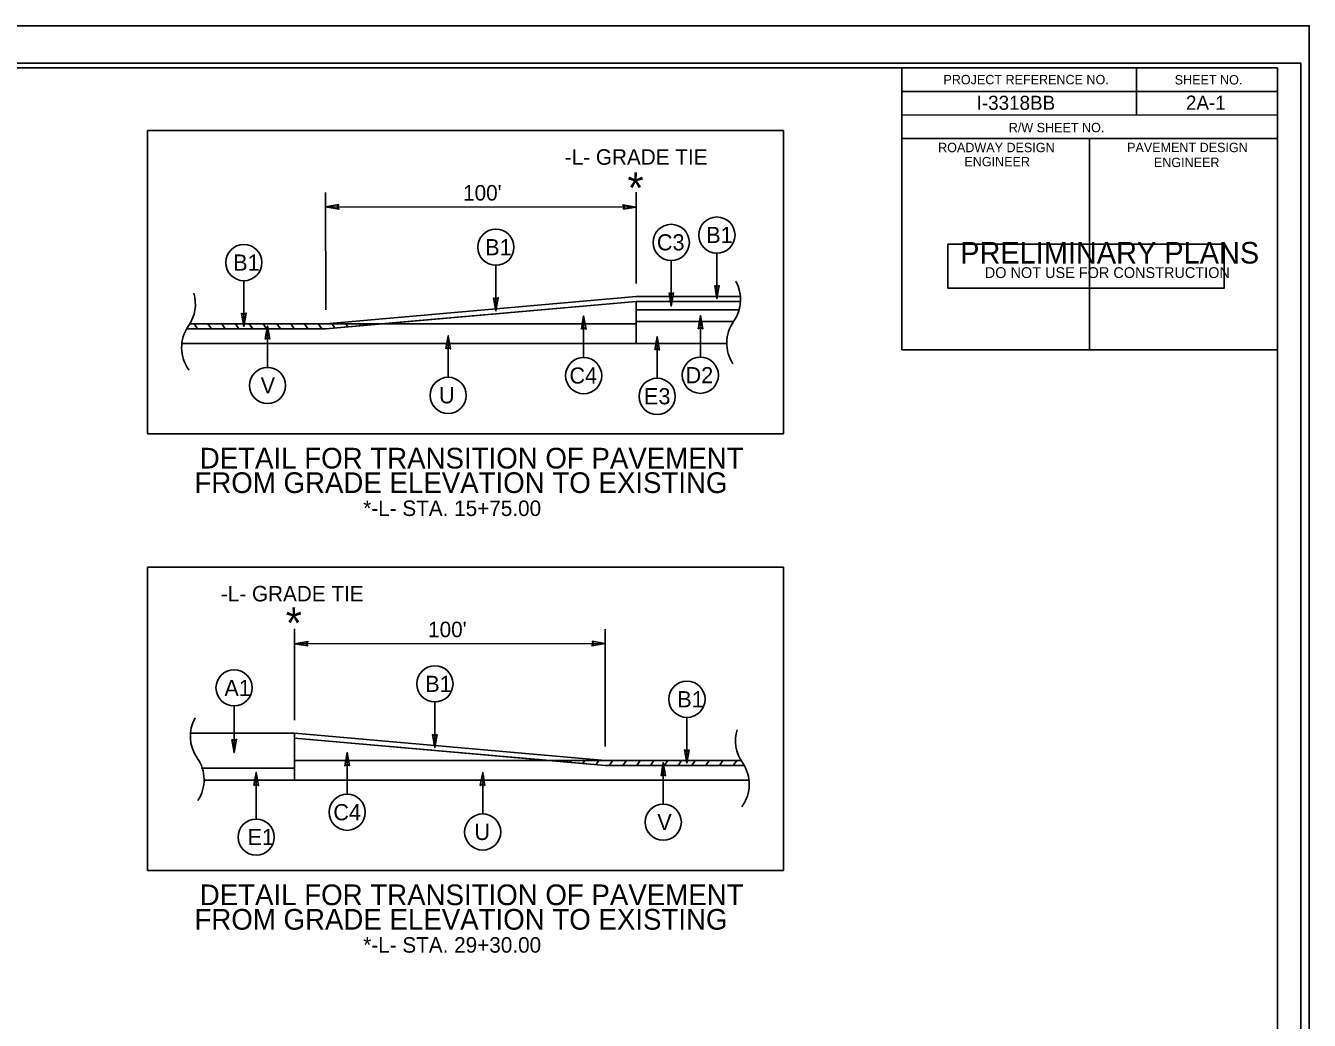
# Model space of a CAD drawing. Extents: x 2241081 to 2251104, y 658534 to 663427.
# Drawn here: x 2248635 to 2249319, y 662385 to 662914 of the extents above; entities that cross this region are included whole.
import ezdxf

# ---------------------------------------------------------------- set-up
doc = ezdxf.new("R2010")
doc.units = 0
for name, color, linetype in [('Old_Level_2', 7, 'Continuous'), ('Prop Dimension Text', 7, 'Continuous'), ('Prop Shade Medium', 7, 'Continuous'), ('Sheet Cutting Line CELL', 7, 'Continuous'), ('Sheet Data Field CELL', 7, 'Continuous'), ('Sheet Plan CELL', 7, 'Continuous'), ('Sheet Plot Border Inside CELL', 7, 'Continuous'), ('Sheet Plot Border Outside CELL', 7, 'Continuous'), ('Sheet Sticker Preliminary CELL', 7, 'Continuous'), ('Typical ID Circle CELL', 7, 'Continuous'), ('Typical Terminator CELL', 7, 'Continuous'), ('Typical Text ID Circle CELL', 7, 'Continuous'), ('Typical Text Label CELL', 7, 'Continuous')]:
    doc.layers.add(name, color=color, linetype=linetype)

msp = doc.modelspace()

# ---------------------------------------------------------------- linework, layer by layer
at = {"layer": 'Old_Level_2'}
for p, q in [((2248795.19, 662755.46), (2248960.58, 662770.04)), ((2248960.58, 662770.04), (2249016.04, 662770.04)), ((2248960.58, 662767.43), (2248824.7, 662755.46)), ((2248960.58, 662767.43), (2248960.58, 662744.97)), ((2249016.08, 662767.43), (2248960.58, 662767.43)), ((2249015.34, 662762.91), (2248960.58, 662762.91)), ((2249012.38, 662756.78), (2248960.58, 662756.78)), ((2248795.19, 662752.86), (2248721.13, 662752.86)), ((2248795.19, 662755.46), (2248722.82, 662755.46)), ((2248726.96, 662752.86), (2248725.12, 662755.46)), ((2248734.31, 662752.86), (2248732.47, 662755.46)), ((2248741.66, 662752.86), (2248739.82, 662755.46)), ((2248749, 662752.86), (2248747.17, 662755.46)), ((2248756.35, 662752.86), (2248754.51, 662755.46)), ((2248763.7, 662752.86), (2248761.86, 662755.46)), ((2248771.05, 662752.86), (2248769.21, 662755.46)), ((2248778.4, 662752.86), (2248776.56, 662755.46)), ((2248785.74, 662752.86), (2248783.91, 662755.46)), ((2248793.09, 662752.86), (2248791.31, 662755.38)), ((2248795.19, 662755.46), (2248960.58, 662755.46)), ((2248795.19, 662752.86), (2248824.7, 662755.46)), ((2248800.13, 662753.29), (2248798.6, 662755.46)), ((2248807.05, 662753.9), (2248805.95, 662755.46)), ((2248813.97, 662754.51), (2248813.3, 662755.46)), ((2248820.88, 662755.12), (2248820.64, 662755.46)), ((2248795.19, 662744.97), (2248718.56, 662744.97)), ((2248960.58, 662744.97), (2248795.19, 662744.97)), ((2249008.75, 662744.97), (2248960.58, 662744.97)), ((2248778.62, 662537.54), (2248723.16, 662537.54)), ((2248778.62, 662537.54), (2248778.62, 662512.48)), ((2248778.62, 662537.54), (2248944.01, 662522.96)), ((2248778.62, 662534.93), (2248914.49, 662522.96)), ((2248729.5, 662518.88), (2248778.62, 662518.88)), ((2248944.01, 662522.96), (2248778.62, 662522.96)), ((2248914.49, 662522.96), (2248944.01, 662520.36)), ((2248918.31, 662522.63), (2248918.55, 662522.96)), ((2248925.23, 662522.02), (2248925.9, 662522.96)), ((2248932.15, 662521.41), (2248933.25, 662522.96)), ((2248939.07, 662520.8), (2248940.6, 662522.96)), ((2248944.01, 662522.96), (2249016.38, 662522.96)), ((2248944.01, 662520.36), (2249018.07, 662520.36)), ((2248946.11, 662520.36), (2248947.88, 662522.88)), ((2248953.45, 662520.36), (2248955.29, 662522.96)), ((2248960.8, 662520.36), (2248962.64, 662522.96)), ((2248968.15, 662520.36), (2248969.99, 662522.96)), ((2248975.5, 662520.36), (2248977.33, 662522.96)), ((2248982.84, 662520.36), (2248984.68, 662522.96)), ((2248990.19, 662520.36), (2248992.03, 662522.96)), ((2248997.54, 662520.36), (2248999.38, 662522.96)), ((2249004.89, 662520.36), (2249006.73, 662522.96)), ((2249012.24, 662520.36), (2249014.07, 662522.96)), ((2248730.44, 662512.48), (2248778.62, 662512.48)), ((2248778.62, 662512.48), (2248944.01, 662512.48)), ((2248944.01, 662512.48), (2249020.64, 662512.48))]:
    msp.add_line(p, q, dxfattribs=at)
for centre, start, end in [((2248996.11, 662768.4), 324.70074, 29.41799), ((2248705.8, 662765.97), 324.70074, 17.25348), ((2249028.75, 662745.29), 144.70074, 213.48887), ((2248738.45, 662742.85), 144.70074, 216.62962), ((2248743.09, 662535.91), 150.58188, 215.29913), ((2249033.39, 662533.47), 162.74639, 215.29913), ((2248710.44, 662512.79), 326.511, 35.29913), ((2249000.75, 662510.36), 323.37025, 35.29913)]:
    msp.add_arc(centre, 20, start, end, dxfattribs=at)
at = {"layer": 'Prop Dimension Text'}
for p, q in [((2249038.95, 662858.49), (2248700.25, 662858.49)), ((2248700.25, 662858.49), (2248700.25, 662697.01)), ((2249038.95, 662858.49), (2249038.95, 662697.01)), ((2248795.19, 662762.94), (2248795.15, 662825.46)), ((2248960.57, 662777), (2248960.55, 662825.56)), ((2248795.15, 662817.81), (2248960.55, 662817.71)), ((2249038.95, 662697.01), (2248700.25, 662697.01)), ((2248700.25, 662625.99), (2249038.95, 662625.99)), ((2248700.25, 662625.99), (2248700.25, 662464.51)), ((2249038.95, 662625.99), (2249038.95, 662464.51)), ((2248778.62, 662544.51), (2248778.65, 662593.07)), ((2248944.01, 662530.44), (2248944.05, 662592.97)), ((2248944.04, 662585.31), (2248778.65, 662585.21)), ((2248700.25, 662464.51), (2249038.95, 662464.51))]:
    msp.add_line(p, q, dxfattribs=at)
at = {"layer": 'Prop Shade Medium'}
for p, q in [((2248795.19, 662755.46), (2248960.58, 662770.04)), ((2248960.58, 662770.04), (2249016.04, 662770.04)), ((2248960.58, 662767.43), (2248795.19, 662752.86)), ((2249016.08, 662767.43), (2248960.58, 662767.43)), ((2248795.19, 662752.86), (2248721.13, 662752.86)), ((2248722.82, 662755.46), (2248795.19, 662755.46)), ((2248944.01, 662522.96), (2248778.62, 662537.54)), ((2248778.62, 662537.54), (2248778.62, 662534.93)), ((2248778.62, 662534.93), (2248944.01, 662520.36)), ((2249016.38, 662522.96), (2248944.01, 662522.96)), ((2248944.01, 662520.36), (2249018.07, 662520.36))]:
    msp.add_line(p, q, dxfattribs=at)
for centre, start, end in [((2248996.11, 662768.4), 357.21688, 4.70058), ((2248738.45, 662742.85), 144.70074, 149.97992), ((2248705.8, 662765.97), 324.70074, 328.30545), ((2249033.39, 662533.47), 211.69442, 215.29913), ((2249000.75, 662510.36), 30.01995, 35.29913)]:
    msp.add_arc(centre, 20, start, end, dxfattribs=at)
at = {"layer": 'Sheet Cutting Line CELL'}
msp.add_line((2249319.01, 662914.26), (2247635.51, 662914.27), dxfattribs=at)
at = {"layer": 'Sheet Plan CELL'}
for p, q in [((2249226.97, 662891.71), (2249227.02, 662866.71)), ((2249101.95, 662879.24), (2249302, 662879.23)), ((2249101.96, 662866.7), (2249302, 662866.73)), ((2249101.96, 662866.7), (2249302, 662866.73)), ((2249101.96, 662866.7), (2249101.96, 662854.21)), ((2249202.01, 662854.21), (2249202.02, 662741.75))]:
    msp.add_line(p, q, dxfattribs=at)
for points in [[(2247802, 661841.78), (2247801.97, 662891.75), (2249101.96, 662891.79), (2249101.97, 662741.73), (2249302.01, 662741.71), (2249302.01, 661841.78)], [(2249302.03, 662891.78), (2247802, 662891.78), (2247802, 661841.78), (2249302.01, 661841.78)], [(2249101.96, 662891.79), (2249302.03, 662891.78), (2249302, 662866.73), (2249101.96, 662866.7)], [(2249101.96, 662854.21), (2249202.01, 662854.21), (2249202.01, 662741.7), (2249101.97, 662741.73)], [(2249202.01, 662854.21), (2249302, 662854.23), (2249302.01, 662741.71), (2249202.01, 662741.7)]]:
    msp.add_lwpolyline(points, close=True, dxfattribs=at)
at = {"layer": 'Sheet Plot Border Inside CELL'}
msp.add_lwpolyline([(2247648.51, 661839.27), (2249314.5, 661839.28), (2249314.51, 662894.26), (2247648.51, 662894.27)], close=True, dxfattribs=at)
at = {"layer": 'Sheet Plot Border Outside CELL'}
msp.add_lwpolyline([(2247635.51, 661819.27), (2249319.01, 661819.26), (2249319.01, 662914.26), (2247635.51, 662914.27)], close=True, dxfattribs=at)
at = {"layer": 'Sheet Sticker Preliminary CELL'}
msp.add_lwpolyline([(2249126.58, 662774.46), (2249126.58, 662797.96), (2249273.58, 662797.96), (2249273.58, 662774.46)], close=True, dxfattribs=at)
at = {"layer": 'Typical ID Circle CELL'}
for p, q in [((2249003.54, 662793.16), (2249003.54, 662768.83)), ((2248885.83, 662786.68), (2248885.83, 662762.35)), ((2248979.22, 662789.27), (2248979.22, 662764.94)), ((2248751.62, 662778.48), (2248751.62, 662754.15)), ((2248932.56, 662737.55), (2248932.56, 662759.69)), ((2248994.7, 662737.74), (2248994.7, 662759.89)), ((2248764.24, 662732.29), (2248764.24, 662754.44)), ((2248860.42, 662727.05), (2248860.42, 662749.19)), ((2248971.66, 662726.51), (2248971.66, 662748.65)), ((2248746.37, 662552.09), (2248746.37, 662527.24)), ((2248853.36, 662554.19), (2248853.36, 662529.86)), ((2248987.58, 662545.99), (2248987.58, 662521.66)), ((2248806.63, 662505.05), (2248806.63, 662527.2)), ((2248974.96, 662499.8), (2248974.96, 662521.94)), ((2248758.18, 662491.85), (2248758.18, 662516.71)), ((2248878.78, 662494.55), (2248878.78, 662516.69))]:
    msp.add_line(p, q, dxfattribs=at)
for centre in [(2249003.54, 662802.78), (2248885.83, 662796.3), (2248979.22, 662798.88), (2248751.62, 662788.1), (2248932.56, 662727.93), (2248994.7, 662728.13), (2248764.24, 662722.68), (2248860.42, 662717.43), (2248971.66, 662716.9), (2248853.36, 662563.8), (2248746.37, 662561.71), (2248987.58, 662555.6), (2248806.63, 662495.44), (2248974.96, 662490.18), (2248758.18, 662482.24), (2248878.78, 662484.94)]:
    msp.add_circle(centre, 9.62, dxfattribs=at)
at = {"layer": 'Typical Terminator CELL'}
for points in [[(2248802.18, 662819.03), (2248795.15, 662817.81), (2248802.22, 662816.56), (2248801.32, 662817.81)], [(2248953.52, 662816.49), (2248960.55, 662817.71), (2248953.48, 662818.95), (2248954.38, 662817.71)], [(2248978.01, 662771.97), (2248979.22, 662764.94), (2248980.47, 662772.01), (2248979.22, 662771.11)], [(2249002.33, 662775.86), (2249003.54, 662768.83), (2249004.79, 662775.9), (2249003.54, 662775)], [(2248884.62, 662769.38), (2248885.83, 662762.35), (2248887.08, 662769.42), (2248885.83, 662768.52)], [(2248750.41, 662761.18), (2248751.62, 662754.15), (2248752.87, 662761.22), (2248751.62, 662760.32)], [(2248931.35, 662752.66), (2248932.56, 662759.69), (2248933.81, 662752.62), (2248932.56, 662753.52)], [(2248993.48, 662752.86), (2248994.7, 662759.89), (2248995.95, 662752.82), (2248994.7, 662753.72)], [(2248765.45, 662747.41), (2248764.24, 662754.44), (2248762.99, 662747.37), (2248764.24, 662748.27)], [(2248859.21, 662742.16), (2248860.42, 662749.19), (2248861.67, 662742.12), (2248860.42, 662743.02)], [(2248970.45, 662741.62), (2248971.66, 662748.65), (2248972.91, 662741.58), (2248971.66, 662742.48)], [(2248785.68, 662584), (2248778.65, 662585.21), (2248785.72, 662586.46), (2248784.82, 662585.21)], [(2248937.02, 662586.53), (2248944.04, 662585.31), (2248936.97, 662584.07), (2248937.87, 662585.32)], [(2248745.16, 662534.27), (2248746.37, 662527.24), (2248747.62, 662534.31), (2248746.37, 662533.41)], [(2248854.57, 662536.89), (2248853.36, 662529.86), (2248852.11, 662536.93), (2248853.36, 662536.03)], [(2248807.85, 662520.17), (2248806.63, 662527.2), (2248805.39, 662520.13), (2248806.63, 662521.03)], [(2248988.79, 662528.69), (2248987.58, 662521.66), (2248986.33, 662528.73), (2248987.58, 662527.83)], [(2248973.75, 662514.91), (2248974.96, 662521.94), (2248976.21, 662514.87), (2248974.96, 662515.77)], [(2248756.97, 662509.68), (2248758.18, 662516.71), (2248759.43, 662509.64), (2248758.18, 662510.54)], [(2248879.99, 662509.66), (2248878.78, 662516.69), (2248877.53, 662509.62), (2248878.78, 662510.52)]]:
    msp.add_lwpolyline(points, close=True, dxfattribs=at)

# ---------------------------------------------------------------- texts
at = {"layer": 'Prop Dimension Text'}
for rotation, p in [(0.03489, (2248868.36, 662821.16)), (359.96498, (2248849.72, 662588.68))]:
    msp.add_text("100'", height=8.25, rotation=rotation, dxfattribs=at).set_placement(p)
at = {"layer": 'Sheet Data Field CELL'}
for s, p in [('I-3318BB', (2249141.84, 662869.46)), ('2A-1', (2249253.31, 662869.53))]:
    msp.add_text(s, height=7.5, rotation=359.99994, dxfattribs=at).set_placement(p)
at = {"layer": 'Sheet Plan CELL'}
for s, height, p in [('PROJECT REFERENCE NO.', 5.0001, (2249124.16, 662883.06)), ('SHEET NO.', 5, (2249247.32, 662882.95)), ('R/W SHEET NO.', 5.0001, (2249158.96, 662857.51)), ('ROADWAY DESIGN', 5.0001, (2249121.33, 662846.91)), ('PAVEMENT DESIGN', 5.0001, (2249221.96, 662846.94)), ('ENGINEER', 5, (2249135.32, 662839.38)), ('ENGINEER', 5, (2249236.23, 662838.98))]:
    msp.add_text(s, height=height, rotation=359.99994, dxfattribs=at).set_placement(p)
at = {"layer": 'Sheet Sticker Preliminary CELL'}
for s, height, p in [('PRELIMINARY PLANS', 11.52, (2249133.08, 662787.61)), ('DO NOT USE FOR CONSTRUCTION', 5.76, (2249146.18, 662779.91))]:
    msp.add_text(s, height=height, rotation=359.99993, dxfattribs=at).set_placement(p)
at = {"layer": 'Typical Text ID Circle CELL'}
for s, height, p in [('B1', 8.608, (2248997.85, 662798.51)), ('B1', 8.608, (2248880.14, 662792.03)), ('C3', 8.608, (2248971.57, 662794.61)), ('B1', 8.608, (2248745.93, 662783.83)), ('C4', 8.608, (2248924.97, 662723.7)), ('D2', 8.608, (2248986.85, 662723.89)), ('V', 8.61, (2248760.57, 662718.44)), ('U', 8.61, (2248855.52, 662713.19)), ('E3', 8.608, (2248964.7, 662712.66)), ('A1', 8.608, (2248741.24, 662557.34)), ('B1', 8.608, (2248848.23, 662559.53)), ('B1', 8.608, (2248982.44, 662551.33)), ('C4', 8.608, (2248799.24, 662491.2)), ('V', 8.61, (2248971.78, 662485.95)), ('E1', 8.608, (2248753.61, 662478)), ('U', 8.61, (2248874.4, 662480.7))]:
    msp.add_text(s, height=height, rotation=359.99993, dxfattribs=at).set_placement(p)
at = {"layer": 'Typical Text Label CELL'}
for s, height, p in [('-L- GRADE TIE', 8.25, (2248922.52, 662840.22)), ('*', 16.5, (2248955.92, 662819.66))]:
    msp.add_text(s, height=height, rotation=359.99987, dxfattribs=at).set_placement(p)
for s, height, p in [('DETAIL FOR TRANSITION OF PAVEMENT', 11.0106, (2248728.12, 662678.49)), ('FROM GRADE ELEVATION TO EXISTING', 11.0106, (2248725.28, 662665.44)), ('*-L- STA. 15+75.00', 8.25, (2248815.16, 662653.2)), ('-L- GRADE TIE', 8.25, (2248739.37, 662607.73)), ('*', 16.5, (2248773.88, 662588.02)), ('DETAIL FOR TRANSITION OF PAVEMENT', 11.0106, (2248728.12, 662446)), ('FROM GRADE ELEVATION TO EXISTING', 11.0106, (2248725.28, 662432.94)), ('*-L- STA. 29+30.00', 8.25, (2248815.16, 662420.71))]:
    msp.add_text(s, height=height, dxfattribs=at).set_placement(p)

doc.saveas('drawing.dxf')
